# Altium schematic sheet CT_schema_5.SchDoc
size 212 x 173 mm
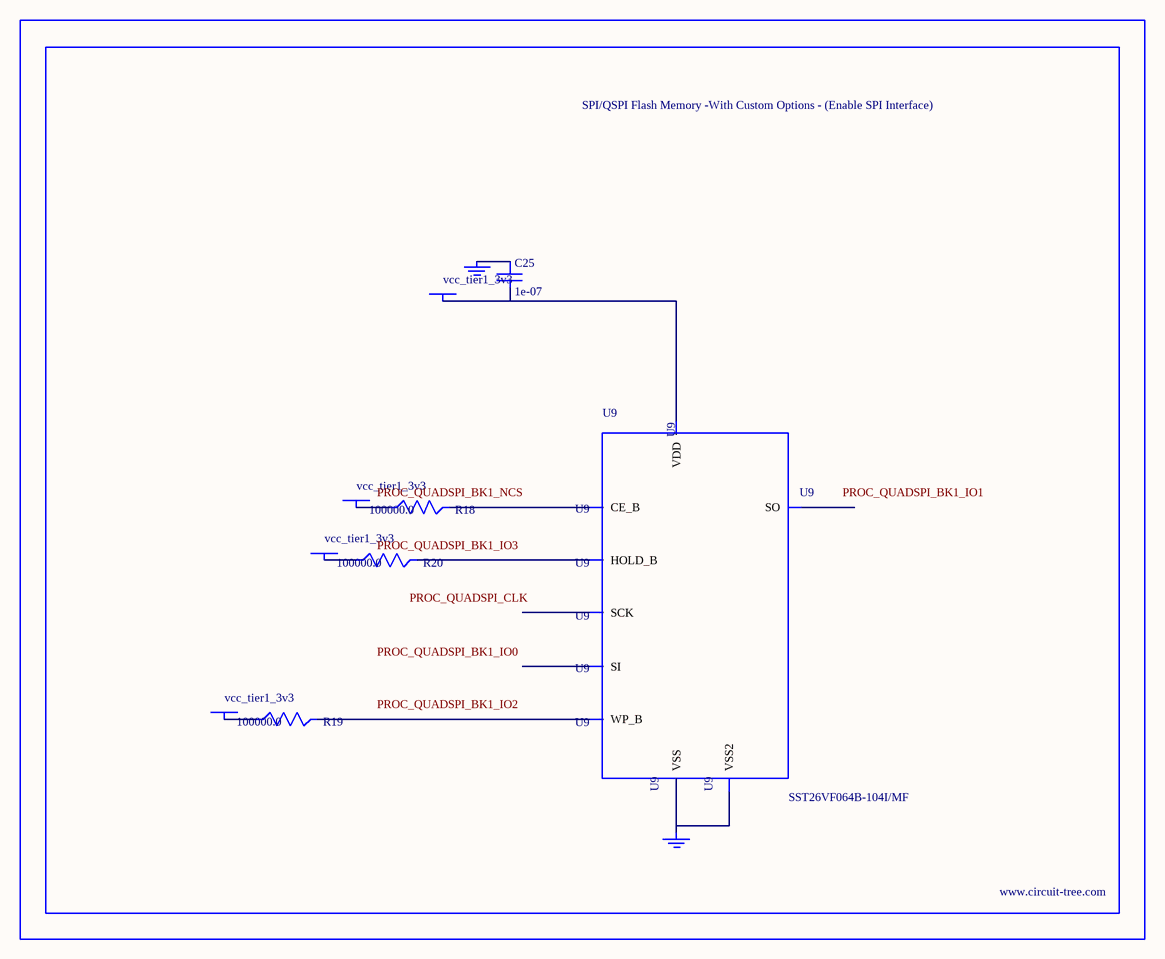
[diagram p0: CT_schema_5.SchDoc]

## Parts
BORDER4  (no value)
C25  1e-07  [C0402]
GND_INSTANCE_4_0  (no value)
GND_INSTANCE_4_1  (no value)
POWER_INSTANCE_4_0  vcc_tier1_3v3
POWER_INSTANCE_4_1  vcc_tier1_3v3
POWER_INSTANCE_4_2  vcc_tier1_3v3
POWER_INSTANCE_4_3  vcc_tier1_3v3
R18  100000.0  [R0603]
R19  100000.0  [R0603]
R20  100000.0  [R0603]
U9  SST26VF064B-104I/MF  [WFDN-8]

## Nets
NetC25_1: C25.1 GND_INSTANCE_4_0.0(GND)
NetC25_2: C25.2 POWER_INSTANCE_4_3.0(PWR) U9.8(VDD)
NetGND_INSTANCE_4_1_0: GND_INSTANCE_4_1.0(GND) U9.4(VSS) U9.9(VSS2)
NetPOWER_INSTANCE_4_0_0: POWER_INSTANCE_4_0.0(PWR) R18.1
NetPOWER_INSTANCE_4_1_0: POWER_INSTANCE_4_1.0(PWR) R19.1
NetPOWER_INSTANCE_4_2_0: POWER_INSTANCE_4_2.0(PWR) R20.1
NetR18_2: R18.2 U9.1(CE_B)
NetR19_2: R19.2 U9.3(WP_B)
NetR20_2: R20.2 U9.7(HOLD_B)

Not connected (* = marked no-connect by the designer): U9 2(SO) 5(SI) 6(SCK)

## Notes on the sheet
- Labels drawn without touching a wire or pin: PROC_QUADSPI_BK1_IO0, PROC_QUADSPI_BK1_IO1, PROC_QUADSPI_BK1_IO2, PROC_QUADSPI_BK1_IO3, PROC_QUADSPI_BK1_NCS, PROC_QUADSPI_CLK

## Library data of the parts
BORDER4 = BORDER_PAGE4
C25 = C0402C104K3RACTU
GND_INSTANCE_4_0 GND_INSTANCE_4_1 = GND
POWER_INSTANCE_4_0-POWER_INSTANCE_4_3 = PWR
R18-R20 = RC0603JR-07100KL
